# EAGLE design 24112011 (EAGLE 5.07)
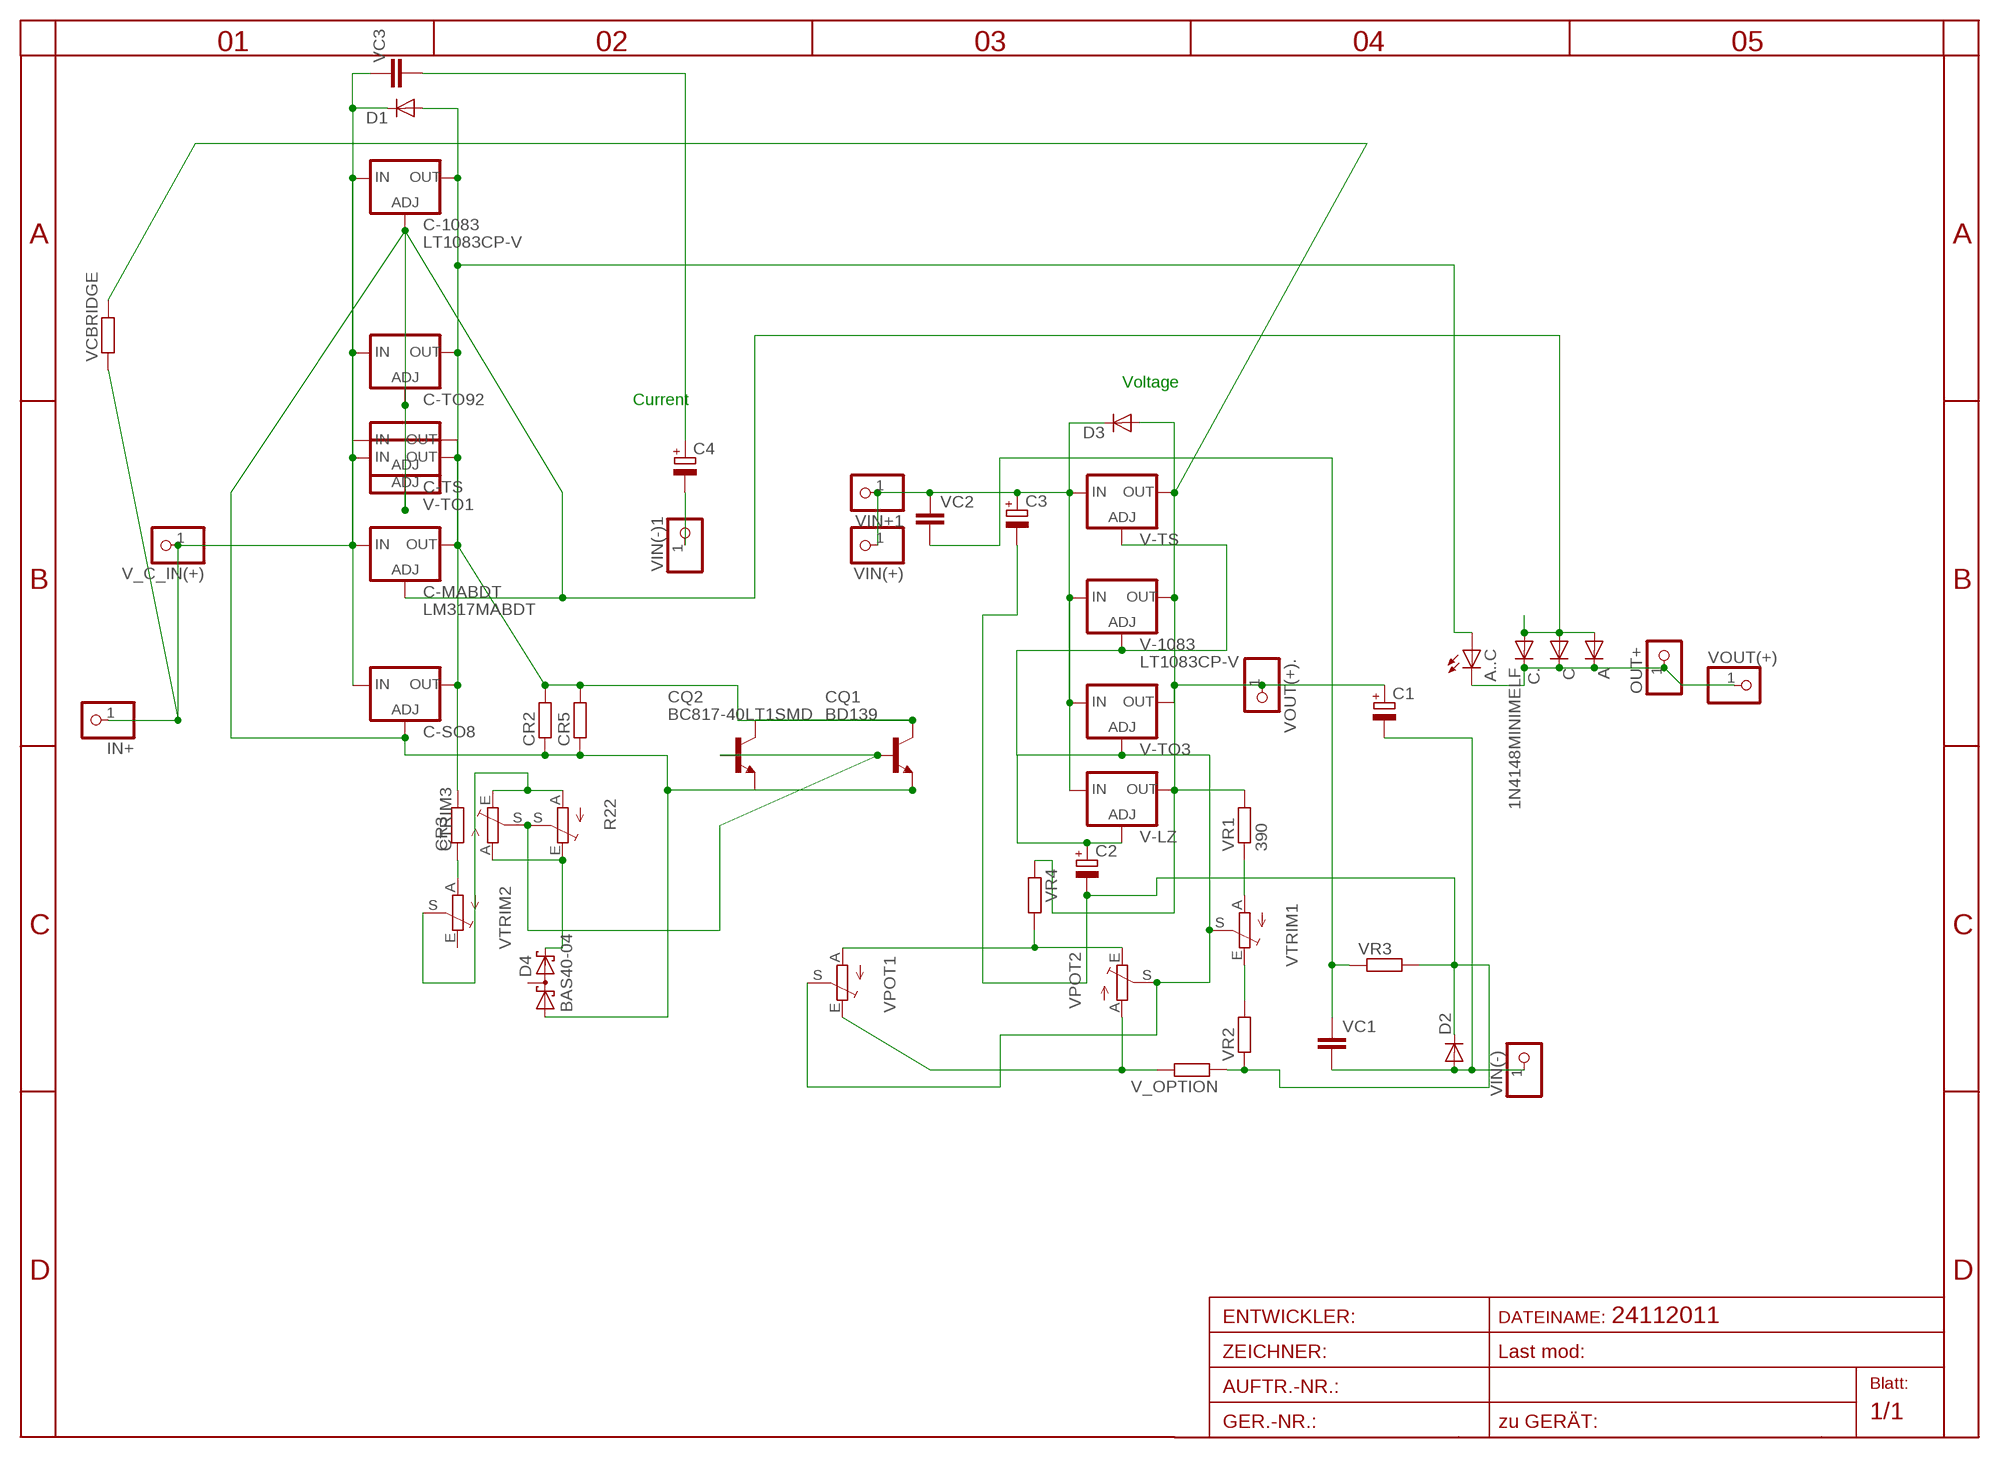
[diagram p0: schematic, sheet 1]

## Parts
A  DIODE-TO220V  [TO220ACS]
A..C  LED3MM  [LED3MM]
C  DIODE-SMB  [SMB]
C1  CPOL-EUE5-8.5  [E5-8,5]
C2  CPOL-EUE2.5-6  [E2,5-6]
C3  CPOL-EUE2.5-6  [E2,5-6]
C4  CPOL-EUE2.5-6  [E2,5-6]
C-1083  LT1083CP-V  [TO247S]
C-MABDT  LM317MABDT  [DPACK]
C-SO8  LM317LM-OUTPIN7  [SO08]
C-TO92  LM317LZ  [317L]
C-TS  LM317TS  [317TS]
C.  1N4148MINIMELF  [MINIMELF]
CQ1  BD139  [TO126V]
CQ2  BC817-40LT1SMD  [SOT23-BEC]
CR2  R-EU_R1206  [R1206]
CR3  R-EU_R1206  [R1206]
CR5  R-EU_R1206  [R1206]
CTRIM3  TRIM_EU-S64W  [S64W]
D1  DIODE-MINIMELF  [MINIMELF]
D2  DIODE-MINIMELF  [MINIMELF]
D3  DIODE-MINIMELF  [MINIMELF]
D4  BAS40-04  [SOT23]
IN+  PINHD-1X1  [1X01]
OUT+  PINHD-1X1  [1X01]
R22  TRIM_EU-RAND160  [RANDL]
V-1083  LT1083CP-V  [TO247S]
V-LZ  LM317LZ  [317L]
V-TO1  LM317-TO3  [TO3-K02]
V-TO3  LM317-TO3  [TO3-K02]
V-TS  LM317TS  [317TS]
V_C_IN(+)  PINHD-1X11MM6  [1X1MM8]
V_OPTION  R-EU_R0402  [R0402]
VC1  C-EU050-025X075  [C050-025X075]
VC2  C-EU050-025X075  [C050-025X075]
VC3  C-EUC1206  [C1206]
VCBRIDGE  R-EU_R0402  [R0402]
VIN(+)  PINHD-1X11MM6  [1X1MM8]
VIN(-)  PINHD-1X1  [1X01]
VIN(-)1  PINHD-1X1  [1X01]
VIN+1  PINHD-1X1  [1X01]
VOUT(+)  PINHD-1X11MM6  [1X1MM8]
VOUT(+).  PINHD-1X11MM6  [1X1MM8]
VPOT1  TRIM_EU-RAND160  [RANDL]
VPOT2  TRIM_EU-S64W  [S64W]
VR1  390  R-EU_0207/12  [0207/12]
VR2  R-EU_0204/7  [0204/7]
VR3  R-EU_0204/5  [0204/5]
VR4  R-EU_0204/7  [0204/7]
VTRIM1  TRIM_EU-EVND_H  [EVND8AA]
VTRIM2  TRIM_EU-EVND_H  [EVND8AA]

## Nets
ADJ2: C2.+ V-1083.1(ADJ) V-LZ.1(ADJ) V-TO3.2(ADJ) V-TS.1(ADJ) VPOT1.S VPOT2.S VTRIM1.S
ADJUST: A.A C-1083.1(ADJ) C-MABDT.1(ADJ) C-SO8.4(ADJ) C-TO92.1(ADJ) C-TS.1(ADJ) C..A C.A CQ1.3(E) CQ2.E CR2.1 CR5.1 D4.1(A1) V-TO1.2(ADJ)
B1: CQ1.1(B) CQ2.B CTRIM3.S R22.S
IN+1: C3.+ D3.C V-1083.3(IN) V-LZ.3(IN) V-TO3.1(IN) V-TS.3(IN) VC2.1 VIN(+).1 VIN+1.1
IN-: C1.- D2.A VC1.2 VIN(-).1
INPUT+: C-1083.3(IN) C-MABDT.3(IN) C-SO8.1(IN) C-TO92.3(IN) C-TS.3(IN) D1.C IN+.1 V-TO1.1(IN) V_C_IN(+).1 VC3.1 VCBRIDGE.1
MINUS: CTRIM3.A D4.2(C2) R22.E
N$1: V_OPTION.2 VPOT1.E VPOT2.A
N$2: VPOT1.A VPOT2.E VR4.2
N$3: VR2.2 VTRIM1.E
N$4: VR1.1 VTRIM1.A
N$5: CTRIM3.E R22.A VTRIM2.S
N$6: CR3.1 VTRIM2.A
N$7: VC1.1 VC2.2 VR3.1
N$8: C4.+ VC3.2
N$9: C4.- VIN(-)1.1
OUT1: A..C.A C-1083.2(OUT) C-MABDT.4(OUT) C-SO8.7(OUT) C-TO92.2(OUT) C-TS.2(OUT) CQ1.2(C) CQ2.C CR2.2 CR3.2 CR5.2 D1.A V-TO1.3(OUT)
OUT2: C1.+ D3.A V-1083.2(OUT) V-LZ.2(OUT) V-TO3.3(OUT) V-TS.2(OUT) VCBRIDGE.2 VOUT(+)..1 VR1.2 VR4.1
OUT+: A..C.K(C) A.C C..C C.C OUT+.1 VOUT(+).1
VIRT-: C2.- C3.- D2.C V_OPTION.1 VR2.1 VR3.2
Unconnected: D4.3(C1A2) VTRIM2.E

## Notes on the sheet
- Voltage
- Current

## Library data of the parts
A C D1-D3 = diode:DIODE-: DIODE
A..C = led:LED: LED
C1-C4 = rcl:CPOL-EU: POLARIZED CAPACITOR, European symbol
C-1083 V-1083 = linear-technology-2:LT1083*: 7.5A Low Dropout Positive Adjustable Regulators
C-MABDT = v-reg:LM317?*: 500 mA Adjustable Output Positive Voltage Regulator Source: http://www.onsemi.co.jp .. LM317M-D.PDF
C-SO8 C-TO92 V-LZ = v-reg-3:LM317L: Adjustable Voltage Regulator, 1.2V to 37V, 100mA
C-TS V-TS = v-reg:LM317TS: VOLTAGE REGULATOR
C. = diode-1:1N4148: DIODE
CQ1 = transistor-npn:BD139*: NPN Transistor
CQ2 = transistor-npn:BC817*: NPN Transistor
CR2 CR3 CR5 V_OPTION VCBRIDGE VR1-VR4 = rcl-2:R-EU_: RESISTOR, European symbol
CTRIM3 R22 VPOT1 VPOT2 VTRIM1 VTRIM2 = pot:TRIM_EU-: POTENTIOMETER
D4 = diode:BAS40-04: Silicon Schottky Diodes General-purpose diode for high-speed switching
IN+ OUT+ VIN(-) VIN(-)1 VIN+1 = pinhead(2):PINHD-1X1: PIN HEADER
V-TO1 V-TO3 = v-reg:LM317-TO3: VOLTAGE REGULATOR
V_C_IN(+) VIN(+) VOUT(+) VOUT(+). = pinhead:PINHD-1X1: PIN HEADER
VC1-VC3 = rcl:C-EU: CAPACITOR, European symbol

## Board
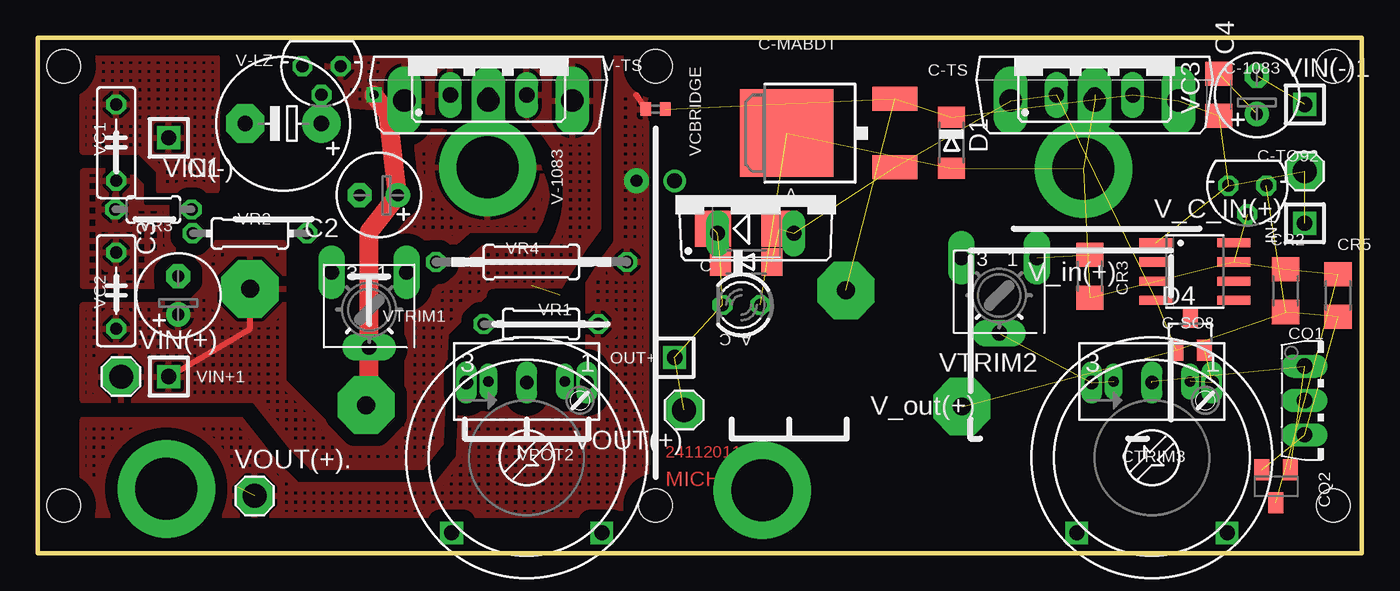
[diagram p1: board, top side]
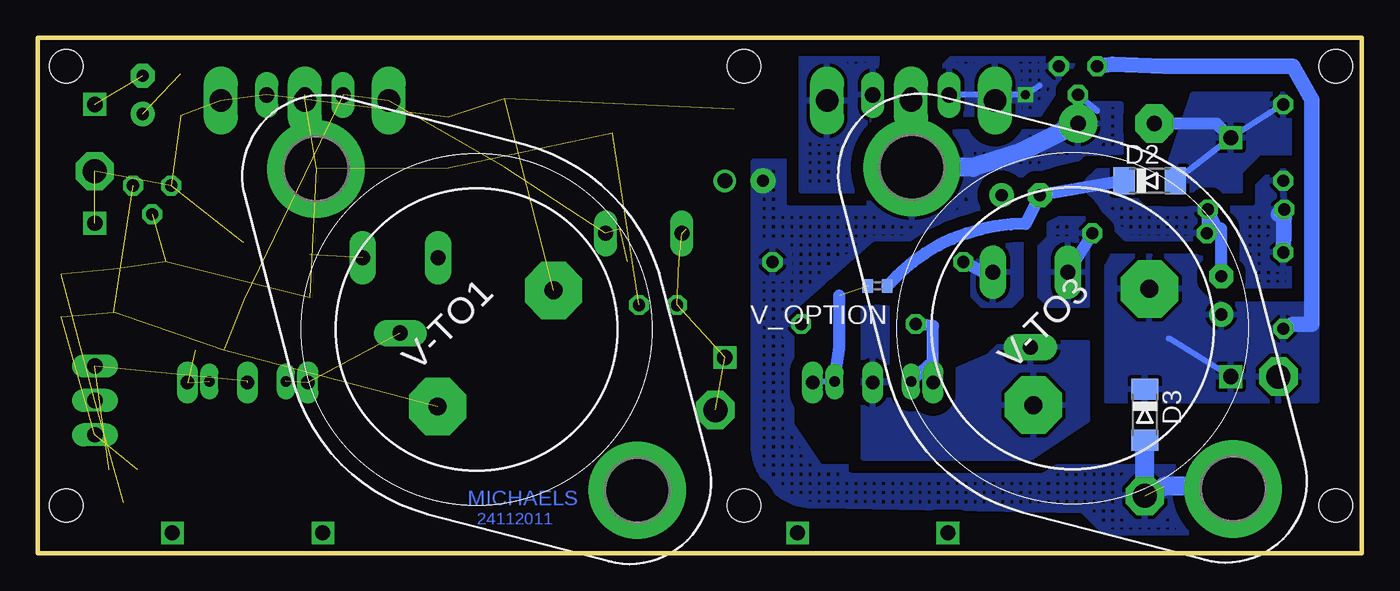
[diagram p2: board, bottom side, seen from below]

Size 88.1 x 34.29 mm. Coordinates in mm from the lower left corner, seen from the top.
Outline: 0,0 88.1,0 88.1,34.29 0,34.29 0,0
Copper layers (1*16): Top 0.035mm / dielectric 1.5mm / Bottom 0.035mm
Design rules "default": minimum track width 10mil, minimum drill 24mil, track to track 8mil, track to pad 8mil, pad to pad 8mil, via to via 8mil, smd to smd 8mil, copper to edge 40mil, drill to drill 8mil, minimum pad ring 10mil, minimum via ring 8mil, stop-mask expansion 4mil, vias tented up to drill 0mil, thermal gap 10mil
Holes 2.2 mm at 86.2,32.38 86.2,3.17 86.2,3.17 41.11,32.38 41.11,3.17 1.74,32.38 1.74,3.17

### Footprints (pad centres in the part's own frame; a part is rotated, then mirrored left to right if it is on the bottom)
TO220ACS = drill 1.016 long: A 2.54,-2.54; C -2.54,-2.54
LED3MM = drill 0.813 octagon: A -1.27,0; K 1.27,0
SMB = smd 2.4 x 2.4: A 2.2,0; C -2.2,0
E5-8,5 = drill 1.016 pad 2.54 round: + -2.54,0 | drill 1.016 pad 2.54 octagon: - 2.54,0
E2,5-6 = drill 0.813 pad 1.6 round: + -1.27,0 | drill 0.813 pad 1.6 octagon: - 1.27,0
TO247S = drill 1.499 long: 1 -5.588,-2.921; 2 0,-2.921; 3 5.588,-2.921
DPACK = smd 1.6 x 3: 1 -2.28,-4.8; 3 2.28,-4.8 | smd 5.8 x 6.2: 4 0,2.38
SO08 = smd 0.6 x 2.2: 1 -1.905,-2.6; 2 -0.635,-2.6; 3 0.635,-2.6; 4 1.905,-2.6; 5 1.905,2.6; 6 0.635,2.6; 7 -0.635,2.6; 8 -1.905,2.6
317L = drill 0.813 octagon: 1 -1.27,0; 2 0,1.905; 3 1.27,0
317TS = drill 1.016 long: 1 -2.54,-2.54; 2 0,-2.54; 3 2.54,-2.54
MINIMELF = smd 1.4 x 1.8: A 1.7,0; C -1.7,0
TO126V = drill 1.016 long: 1 -2.286,-1.27; 2 0,-1.27; 3 2.286,-1.27
SOT23-BEC = smd 1 x 1.4: B -0.95,-1.1; C 0,1.1; E 0.95,-1.1
R1206 = smd 1.6 x 1.803: 1 -1.422,0; 2 1.422,0
S64W = drill 0.7 long: A 2.54,1.27; E -2.54,1.27; S 0,1.27
SOT23 = smd 1 x 1.4: 1 -0.95,-1.1; 2 0.95,-1.1; 3 0,1.1
1X01 = drill 1.016 square: 1 0,0
RANDL = drill 0.9 long: A -4,5; E 4,5; S 0,5 | drill 1 square: P$1 -5,-5; P$2 5,-5
TO3-K02 = drill 1.194 pad 3.81 octagon: 1 -1.778,-5.461; 2 -1.778,5.461 | drill 4.115 pad 6.477 round: 3 15.113,0; 3@ -15.113,0
1X1MM8 = drill 1.6 pad 2.54 octagon: 1 0,0
R0402 = smd 0.7 x 0.9: 1 -0.65,0; 2 0.65,0
C050-025X075 = drill 0.813 octagon: 1 -2.54,0; 2 2.54,0
C1206 = smd 1.6 x 1.8: 1 -1.4,0; 2 1.4,0
0207/12 = drill 0.813 octagon: 1 -6.35,0; 2 6.35,0
0204/7 = drill 0.813 octagon: 1 -3.81,0; 2 3.81,0
0204/5 = drill 0.813 octagon: 1 -2.54,0; 2 2.54,0
EVND8AA = drill 1 pad 1.778 long: A -2.5,-2.5; E 2.5,-2.5; S 0,2.5

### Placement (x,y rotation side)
A  47.78,23.81 0 top
A..C  46.83,16.51 180 top
C  47.14,21.59 0 top
C1  16.34,28.57 180 top
C2  22.7,23.81 180 top
C3  9.36,17.14 90 top
C4  81.12,30.48 90 top
C-1083  70.32,33.02 0 top
C-MABDT  52.22,27.94 90 top
C-SO8  76.99,18.73 270 top
C-TO92  80.48,24.45 180 top
C-TS  70.32,33.02 0 top
C.  47.14,19.37 0 top
CQ1  85.56,10.16 270 top
CQ2  82.39,4.45 180 top
CR2  83.02,17.46 90 top
CR3  70,18.41 270 top
CR5  86.51,17.14 90 top
CTRIM3  74.13,10.16 0 top
D1  60.8,27.3 270 top
D2  14.12,24.77 0 bottom
D3  14.44,9.21 270 bottom
D4  76.67,14.61 0 top
IN+  84.29,21.94 0 top
OUT+  42.38,13.02 90 top
R22  74.13,6.35 0 top
V-1083  30,33.02 0 top
V-LZ  18.88,32.38 180 top
V-TO1  58.89,14.88 135 bottom
V-TO3  19.25,14.97 135 bottom
V-TS  30,33.02 0 top
V_C_IN(+)  84.29,25.4 0 top
V_OPTION  32.22,17.78 180 bottom
VC1  5.23,27.3 90 top
VC2  5.23,17.46 90 top
VC3  78.58,30.48 90 top
VCBRIDGE  41.11,29.53 180 top
VIN(+)  5.55,11.75 0 top
VIN(-)  8.72,27.62 0 top
VIN(-)1  84.29,29.84 0 top
VIN+1  8.72,11.75 0 top
VOUT(+)  43.02,9.53 0 top
VOUT(+).  14.44,3.81 0 top
VPOT1  32.54,6.35 0 top
VPOT2  32.54,10.16 0 top
VR1  32.86,19.37 0 top
VR2  14.12,21.27 0 top
VR3  7.71,22.86 0 top
VR4  33.49,15.24 180 top
VTRIM1  22.06,16.19 180 top
VTRIM2  63.97,17.14 180 top

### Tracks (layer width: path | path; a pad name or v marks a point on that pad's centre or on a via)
ADJ2  (via drill 0.6)
  Top 1.27: V-TO3.2 22.06,9.86 22.06,21.39 C2.+ 23.33,29.21 v22.38,30.48
  Bottom 0.406: 24.06,29.75 V-1083.1 24.79,30.48 V-TS.1 | 24.06,29.75 23.52,29.21 | 24.06,29.75 23.33,30.48 v22.38,30.48 21.43,31.11
  pour Bottom (isolate 0.813, hatched): 21.43,29.21 18.88,33.02 27.14,33.02 28.41,31.75 28.41,29.21
  pour Bottom (isolate 0.813, rank 5): 18.25,13.97 23.96,13.97 24.92,13.02 31.58,10.16 31.58,16.51 33.17,16.51 33.17,6.35 22.06,6.35 18.25,8.89
  pour Top (isolate 0.813, hatched): 15.71,33.02 27.14,33.02 28.41,31.75 28.41,30.48 27.14,29.21 15.71,30.16
ADJUST  (13 unrouted)
B1  (3 unrouted)
IN+1
  Top 0.406: V-TO3.1 14.14,14.94 VIN+1.1
  Bottom 0.406: VIN+1.1 12.85,14.29 | 4.6,15.24 VC2.1 | 16.6,32.51 13.42,32.18
  Bottom 1.016: V-LZ.3 16.6,32.51 13.17,32.38 4.6,32.38 3.33,30.16 3.33,27.3 3.33,15.24 4.6,15.24
  pour Bottom (isolate 0.813, hatched): 32.22,33.02 37.3,33.02 37.3,24.13 33.49,24.13
  pour Top (isolate 0.813, rank 3, hatched): 3.01,16.51 8.09,16.51 10.63,20.64 16.34,20.64 16.34,11.43 19.52,8.26 24.6,8.26 24.6,15.88 29.68,20.32 34.12,20.32 arc90 32.22,29.21 32.22,33.02 37.3,33.02 37.3,21.59 36.35,20.32 34.76,17.78 30.31,17.78 arc90 29.68,17.14 27.14,14.61 26.82,7.3 25.55,5.71 18.25,5.71 16.98,6.98 14.44,10.16 3.01,10.16
  pour Bottom (isolate 0.813, rank 4): 16.98,19.05 16.98,10.16 3.01,10.16 3.01,16.51 9.36,16.51 10.63,17.78 10.63,21.59 15.71,21.59
IN-
  Bottom 0.406: VC1.2 VIN(-).1 D2.A
  Bottom 0.813: C1.- 9.68,28.57 VIN(-).1
  pour Bottom (isolate 0.813, rank 2): 4.28,30.48 11.26,30.48 12.85,25.72 12.85,24.13 8.09,24.13 8.09,25.4 6.82,26.67 4.28,26.67
  pour Top (isolate 0.813, hatched): 3.01,33.02 11.9,33.02 11.9,24.13 8.09,24.13 8.09,25.4 6.82,26.67 3.01,26.67
INPUT+  (10 unrouted)
MINUS  (2 unrouted)
N$1  (1 unrouted)
  Bottom 0.406: VPOT2.A 35.9,11.43 VPOT1.E
  Bottom 0.813: 34.76,17.14 34.76,13.65 VPOT2.A
N$2
  Bottom 0.813: VPOT2.E 28.62,12.7 VPOT1.A 28.54,15.11 VR4.2
N$3
  Bottom 0.813: VR2.2 19.52,18.73 VTRIM1.E
  pour Bottom (isolate 0.813, rank 2, hatched): 18.25,22.22 20.15,22.22 20.79,21.91 20.79,20.95 21.43,20.32 21.43,17.14 20.79,16.51 18.25,16.51
N$4
  Bottom 0.813: VTRIM1.A 25.2,18.69 VR1.1
  pour Bottom (isolate 0.813, rank 3, hatched): 22.7,21.59 23.33,21.59 25.87,19.05 25.87,17.14 25.23,16.51 23.33,16.51 22.7,17.14
N$5  (2 unrouted)
N$6  (1 unrouted)
N$7
  Bottom 1.016: VC2.2 VR3.1 5.55,22.54
  pour Bottom (isolate 0.813, rank 3, hatched): 4.28,25.4 4.28,17.78 9.36,17.78 9.36,25.4
  pour Top (isolate 0.813, rank 2, hatched): 3.01,25.4 3.01,17.78 9.36,17.78 9.36,25.4
N$8  (1 unrouted)
N$9  (1 unrouted)
N$10  (via drill 1)
  other vias: 42.38,24.77
OUT1  (12 unrouted)
OUT2  (via drill 0.8 pad 1.68)  (1 unrouted)
  Top 0.406: VCBRIDGE.2 39.84,30.48
  Bottom 0.406: 39.21,24.77 v39.84,24.77 | 29.94,30.04 V-1083.2 V-TS.2 | V-LZ.2 17.61,29.41
  Bottom 1.27: 11.26,4.45 13.17,4.45 | VOUT(+)..1 D3.A | C1.+ 22.7,26.67 25.87,25.66 V-TO3.3 V-1083.2
  pour Bottom (isolate 0.813, rank 6, hatched): 32.22,28.57 33.49,26.67 33.49,25.4 34.76,24.13 37.3,24.13 37.3,26.04 40.48,26.04 40.48,6.98 arc-90 36.03,3.17 18.57,2.86 16.98,1.27 6.19,1.27 6.19,6.35 arc-90 6.82,5.71 36.03,5.71 37.94,8.57 37.94,16.19 32.54,20.95 29.68,20.95 26.5,22.22 22.06,25.4 arc16 16.03,26.67 16.03,29.84 20.47,29.84 20.47,28.57
  pour Top (isolate 0.813, rank 4, hatched): 24.28,29.21 30.95,29.21 33.49,26.67 33.49,25.4 34.76,24.13 37.3,24.13 37.3,33.02 40.48,33.02 40.48,2.54 3.01,2.54 3.01,8.89 15.71,8.89 17.61,5.71 25.87,5.71 28.41,10.16 36.67,10.16 36.67,20.32 36.98,21.59 36.03,21.59 34.76,20.32 28.09,20.64 23.96,20.95 24.28,25.4
OUT+  (5 unrouted)
VIRT-
  Bottom 0.813: 15.71,24.65 D2.C C2.- 22.38,21.91 arc-42 30.63,18.73 30.93,18.43 V_OPTION.1 | VR2.1 VR3.2 9.61,21.59 9.36,21.59 C3.-
  pour Bottom (isolate 0.813, hatched): 15.71,25.4 17.61,25.4 18.25,24.77 18.25,24.13 17.61,23.5 16.34,21.59 15.71,20.95 10.63,20.95 10.63,22.86 14.44,22.86 15.07,23.5

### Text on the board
Top: 24112011 | MICHAELS
Bottom: MICHAELS | 24112011
tNames: V_in(+) | V_out(+)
